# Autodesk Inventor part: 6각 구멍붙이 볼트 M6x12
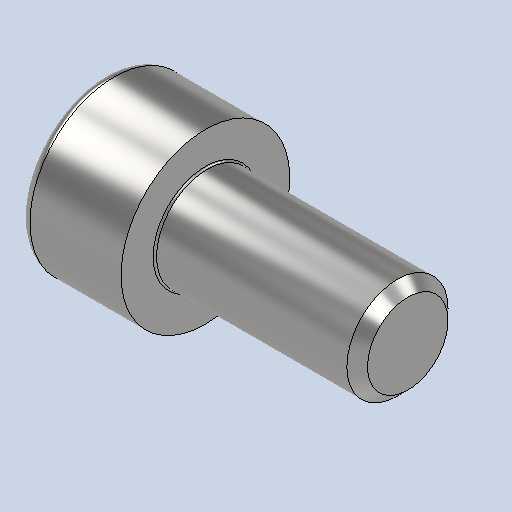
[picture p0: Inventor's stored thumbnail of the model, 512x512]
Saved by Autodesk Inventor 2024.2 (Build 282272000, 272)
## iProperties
Created: 2026-01
Part Number: 6각 구멍붙이 볼트 M6x12
Material: 강철, 연강
Description: 6각머리 태핑 나사
Document SubType Name: Modeling
Designer: home
Density: 7.85 g/cm^3
Appearance: 기본값
Author: jhkim
Sending System: Autodesk Inventor 2026
Preprocessor: ST-DEVELOPER v20.1
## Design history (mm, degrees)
feature "Solid1"
node "솔리드1"
